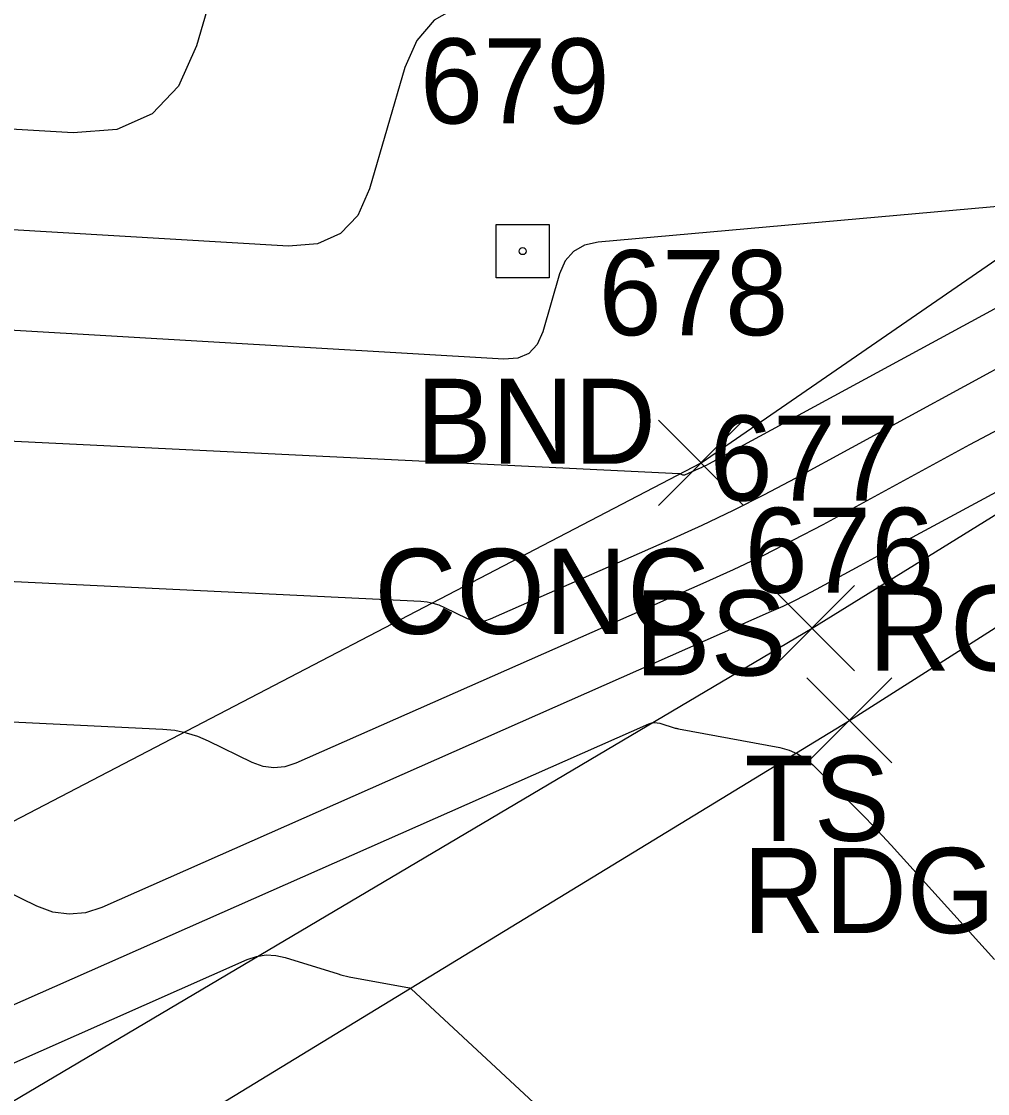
# Model space of a CAD drawing. Extents: x 1650836 to 1652450, y 332578 to 333908.
# Drawn here: x 1652114.39 to 1652137.1, y 332688.37 to 332713.58 of the extents above; entities that cross this region are included whole.
import ezdxf

# ---------------------------------------------------------------- set-up
doc = ezdxf.new("R2010")
doc.units = 0
for name, color, linetype in [('L_A', 7, 'Continuous'), ('L_C', 7, 'Continuous'), ('L_I', 7, 'Continuous'), ('L_TIC', 7, 'Continuous'), ('LELB', 7, 'Continuous'), ('LSOGCMI', 7, 'Continuous'), ('M_A', 7, 'Continuous'), ('M_C', 7, 'Continuous'), ('M_I', 7, 'Continuous'), ('MHBP', 7, 'Continuous'), ('P_A', 7, 'Continuous'), ('P_I', 7, 'Continuous'), ('P_TIC', 7, 'Continuous'), ('PEU', 7, 'Continuous')]:
    doc.layers.add(name, color=color, linetype=linetype)

msp = doc.modelspace()

# ---------------------------------------------------------------- linework, layer by layer
at = {"layer": 'L_TIC'}
for points in [[(1652129.366, 332702.201), (1652131.366, 332704.201)], [(1652131.366, 332702.201), (1652129.366, 332704.201)], [(1652131.975, 332698.313), (1652133.975, 332700.313)], [(1652133.975, 332698.313), (1652131.975, 332700.313)]]:
    msp.add_lwpolyline(points, dxfattribs=at)
at = {"layer": 'LELB'}
for points in [[(1652048.756, 332662.461), (1652082.555, 332678.298), (1652130.366, 332703.201), (1652148.083, 332715.406), (1652159.47, 332726.367), (1652148.02, 332734.227), (1652128.413, 332739.339), (1652116.951, 332747.33), (1652106.793, 332756.875), (1652094.604, 332761.138), (1652083.802, 332764.466), (1652074.482, 332770.284), (1652065.17, 332770.428), (1652062.989, 332774.387), (1652054.537, 332784.724), (1652034.993, 332796.475), (1652025.062, 332801.1), (1652009.772, 332808.074), (1651988.967, 332816.401), (1651980.006, 332832.954), (1651960.575, 332843.477), (1651932.852, 332862.75), (1651890.753, 332886.019), (1651847.527, 332911.35)], [(1652054.928, 332654.589), (1652089.949, 332673.854), (1652132.975, 332699.313), (1652151.656, 332710.875), (1652169.833, 332727.743)]]:
    msp.add_lwpolyline(points, dxfattribs=at)
at = {"layer": 'LSOGCMI'}
for points in [[(1652142.69, 332720.107), (1652133.618, 332720.391), (1652132.294, 332720.413), (1652130.97, 332720.394), (1652129.648, 332720.336), (1652128.327, 332720.238), (1652122.662, 332719.733), (1652121.634, 332719.509), (1652120.809, 332719.038), (1652120.188, 332718.32), (1652119.769, 332717.355), (1652118.5, 332713.002), (1652118.081, 332712.058), (1652117.458, 332711.402), (1652116.632, 332711.036), (1652115.602, 332710.958), (1652104.001, 332711.64)], [(1652145.955, 332715.903), (1652125.305, 332714.061), (1652124.63, 332713.914), (1652124.088, 332713.605), (1652123.68, 332713.133), (1652123.404, 332712.499), (1652122.571, 332709.639), (1652122.295, 332709.019), (1652121.886, 332708.589), (1652121.344, 332708.348), (1652120.667, 332708.297), (1652100.52, 332709.482)], [(1652137.601, 332709.25), (1652127.948, 332708.389), (1652127.625, 332708.319), (1652127.367, 332708.171), (1652127.171, 332707.946), (1652127.04, 332707.643), (1652126.642, 332706.277), (1652126.51, 332705.981), (1652126.315, 332705.775), (1652126.056, 332705.66), (1652125.732, 332705.635), (1652095.639, 332707.405)], [(1652141.213, 332708.963), (1652130.539, 332703.172), (1652130.483, 332703.142), (1652130.425, 332703.113), (1652130.367, 332703.085), (1652130.309, 332703.059), (1652129.977, 332702.912), (1652129.966, 332702.909), (1652129.955, 332702.908), (1652129.945, 332702.909), (1652129.934, 332702.913), (1652129.893, 332702.933), (1652129.882, 332702.938), (1652129.871, 332702.941), (1652129.86, 332702.944), (1652129.849, 332702.945), (1652093.769, 332704.695)], [(1652137.881, 332705.714), (1652132.576, 332702.836), (1652131.852, 332702.452), (1652131.121, 332702.084), (1652130.382, 332701.73), (1652129.636, 332701.392), (1652125.409, 332699.524), (1652125.274, 332699.48), (1652125.139, 332699.467), (1652125.005, 332699.485), (1652124.872, 332699.535), (1652124.341, 332699.794), (1652124.206, 332699.852), (1652124.067, 332699.895), (1652123.925, 332699.924), (1652123.779, 332699.938), (1652093.325, 332701.416)], [(1652142.46, 332705.29), (1652135.13, 332701.336), (1652134.872, 332701.197), (1652134.614, 332701.058), (1652134.357, 332700.918), (1652134.099, 332700.779), (1652133.069, 332700.22), (1652132.81, 332700.083), (1652132.549, 332699.951), (1652132.285, 332699.825), (1652132.018, 332699.704), (1652116.273, 332692.749), (1652115.889, 332692.623), (1652115.507, 332692.586), (1652115.126, 332692.638), (1652114.748, 332692.778), (1652113.236, 332693.516)], [(1652137.372, 332703.995), (1652136.681, 332703.621), (1652135.99, 332703.246), (1652133.227, 332701.747), (1652132.532, 332701.379), (1652131.831, 332701.026), (1652131.122, 332700.687), (1652130.407, 332700.362), (1652120.841, 332696.137), (1652120.581, 332696.052), (1652120.323, 332696.027), (1652120.066, 332696.062), (1652119.81, 332696.156), (1652118.788, 332696.655), (1652118.53, 332696.766), (1652118.264, 332696.849), (1652117.99, 332696.905), (1652117.71, 332696.932), (1652092.881, 332698.137)], [(1652111.705, 332689.361), (1652129.142, 332697.063), (1652129.205, 332697.085), (1652129.27, 332697.095), (1652129.334, 332697.092), (1652129.4, 332697.078), (1652129.759, 332696.966), (1652129.777, 332696.96), (1652129.796, 332696.956), (1652129.815, 332696.951), (1652129.833, 332696.947), (1652132.219, 332696.505), (1652132.436, 332696.448), (1652132.637, 332696.362), (1652132.822, 332696.245), (1652132.992, 332696.098), (1652133.981, 332695.109), (1652134.199, 332694.889), (1652134.413, 332694.666), (1652134.625, 332694.441), (1652134.834, 332694.213), (1652137.266, 332691.521)], [(1652111.658, 332687.97), (1652119.696, 332691.521), (1652119.916, 332691.597), (1652120.139, 332691.63), (1652120.364, 332691.622), (1652120.591, 332691.572), (1652121.833, 332691.184), (1652121.897, 332691.165), (1652121.961, 332691.148), (1652122.026, 332691.133), (1652122.092, 332691.119), (1652123.51, 332690.856), (1652123.522, 332690.853), (1652123.533, 332690.849), (1652123.543, 332690.843), (1652123.552, 332690.835), (1652129.42, 332685.378)]]:
    msp.add_lwpolyline(points, dxfattribs=at)
at = {"layer": 'MHBP'}
msp.add_lwpolyline([(1652125.547, 332708.804), (1652126.797, 332708.804), (1652126.797, 332707.554), (1652125.547, 332707.554)], close=True, dxfattribs=at)
msp.add_circle((1652126.172, 332708.179), 0.0833, dxfattribs=at)
at = {"layer": 'P_TIC'}
for points in [[(1652132.854, 332696.145), (1652134.854, 332698.145)], [(1652134.854, 332696.145), (1652132.854, 332698.145)]]:
    msp.add_lwpolyline(points, dxfattribs=at)
at = {"layer": 'PEU'}
msp.add_lwpolyline([(1652056.971, 332651.823), (1652091.078, 332671.061), (1652133.854, 332697.145), (1652158.219, 332712.634)], dxfattribs=at)

# ---------------------------------------------------------------- texts
at = {"layer": 'L_A'}
for s, p in [('BS', (1652128.807, 332698.201)), ('TS', (1652131.385, 332694.313))]:
    msp.add_text(s, height=2, dxfattribs=at).set_placement(p)
at = {"layer": 'L_C'}
msp.add_text('ROW OF 5 BOXES', height=2, dxfattribs=at).set_placement((1652134.297, 332698.315))
at = {"layer": 'L_I'}
for s, p in [('678', (1652127.956, 332706.201)), ('677', (1652130.566, 332702.313))]:
    msp.add_text(s, height=2, dxfattribs=at).set_placement(p)
at = {"layer": 'M_A'}
msp.add_text('BND', height=2, dxfattribs=at).set_placement((1652123.66, 332703.179))
at = {"layer": 'M_C'}
msp.add_text('CONC', height=2, dxfattribs=at).set_placement((1652122.684, 332699.179))
at = {"layer": 'M_I'}
msp.add_text('679', height=2, dxfattribs=at).set_placement((1652123.755, 332711.179))
at = {"layer": 'P_A'}
msp.add_text('RDG', height=2, dxfattribs=at).set_placement((1652131.342, 332692.145))
at = {"layer": 'P_I'}
msp.add_text('676', height=2, dxfattribs=at).set_placement((1652131.389, 332700.145))

doc.saveas('drawing.dxf')
